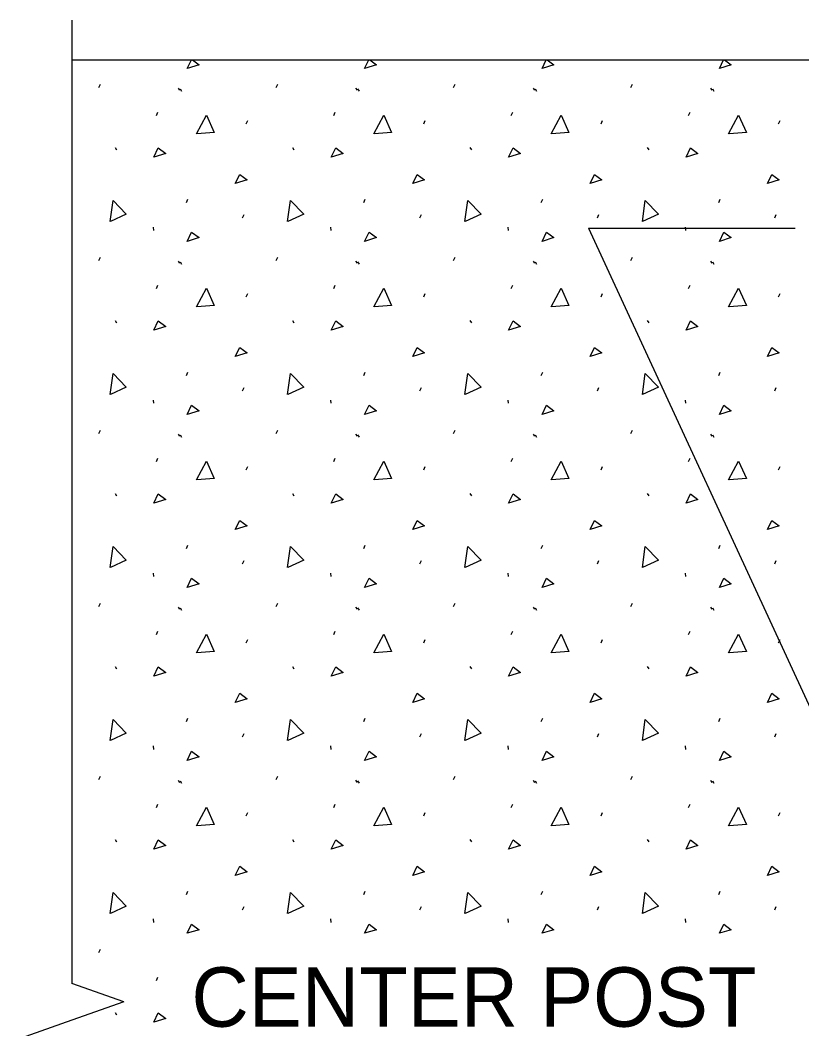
# Model space of a CAD drawing. Extents: x 49991.4 to 50021, y 49987.6 to 50011.4.
# Drawn here: x 50009.655 to 50010.444, y 49996.152 to 49997.171 of the extents above; entities that cross this region are included whole.
import ezdxf

# ---------------------------------------------------------------- set-up
doc = ezdxf.new("R2010")
doc.units = 0
for name, color, linetype in [('Level 1', 7, 'Continuous'), ('Level 2', 7, 'Continuous'), ('Level 3', 7, 'Continuous'), ('Level 6', 7, 'Continuous')]:
    doc.layers.add(name, color=color, linetype=linetype)

msp = doc.modelspace()

# ---------------------------------------------------------------- linework, layer by layer
at = {"layer": 'Level 1'}
for p, q in [((50009.7073, 49997.1307), (50012.0351, 49997.1307)), ((50009.8237, 49997.122), (50009.8279, 49997.1307)), ((50010.0029, 49997.122), (50010.0071, 49997.1307)), ((50010.1821, 49997.122), (50010.1862, 49997.1307)), ((50010.3612, 49997.122), (50010.3654, 49997.1307)), ((50009.7345, 49997.1026), (50009.736, 49997.1059)), ((50009.8146, 49997.1021), (50009.8161, 49997.0998)), ((50009.8166, 49997.1012), (50009.8181, 49997.099)), ((50009.9136, 49997.1026), (50009.9151, 49997.1059)), ((50009.9938, 49997.1021), (50009.9953, 49997.0998)), ((50009.9958, 49997.1012), (50009.9973, 49997.099)), ((50010.0928, 49997.1026), (50010.0943, 49997.1059)), ((50010.173, 49997.1021), (50010.1745, 49997.0998)), ((50010.175, 49997.1012), (50010.1765, 49997.099)), ((50010.2719, 49997.1026), (50010.2734, 49997.1059)), ((50010.3521, 49997.1021), (50010.3536, 49997.0998)), ((50010.3541, 49997.1012), (50010.3556, 49997.099)), ((50009.7926, 49997.0744), (50009.7941, 49997.0778)), ((50009.9718, 49997.0744), (50009.9733, 49997.0778)), ((50010.151, 49997.0744), (50010.1525, 49997.0778)), ((50010.3301, 49997.0744), (50010.3316, 49997.0778)), ((50009.8834, 49997.0658), (50009.8849, 49997.0692)), ((50010.0626, 49997.0658), (50010.0641, 49997.0692)), ((50010.2417, 49997.0658), (50010.2432, 49997.0692)), ((50010.4209, 49997.0658), (50010.4224, 49997.0692)), ((50009.7509, 49997.042), (50009.7524, 49997.0397)), ((50009.79, 49997.0323), (50009.7945, 49997.0416)), ((50009.7945, 49997.0416), (50009.802, 49997.036)), ((50009.93, 49997.042), (50009.9315, 49997.0397)), ((50009.9692, 49997.0323), (50009.9737, 49997.0416)), ((50009.9737, 49997.0416), (50009.9811, 49997.036)), ((50010.1092, 49997.042), (50010.1107, 49997.0397)), ((50010.1483, 49997.0323), (50010.1528, 49997.0416)), ((50010.1528, 49997.0416), (50010.1603, 49997.036)), ((50010.2883, 49997.042), (50010.2898, 49997.0397)), ((50010.3275, 49997.0323), (50010.332, 49997.0416)), ((50010.332, 49997.0416), (50010.3394, 49997.036)), ((50009.802, 49997.036), (50009.79, 49997.0323)), ((50009.9811, 49997.036), (50009.9692, 49997.0323)), ((50010.1603, 49997.036), (50010.1483, 49997.0323)), ((50010.3394, 49997.036), (50010.3275, 49997.0323)), ((50009.823, 49996.9864), (50009.8245, 49996.9898)), ((50010.0021, 49996.9864), (50010.0036, 49996.9898)), ((50010.1813, 49996.9864), (50010.1828, 49996.9898)), ((50010.3605, 49996.9864), (50010.362, 49996.9898)), ((50009.8797, 49996.9711), (50009.8812, 49996.9745)), ((50010.0588, 49996.9711), (50010.0603, 49996.9745)), ((50010.238, 49996.9711), (50010.2395, 49996.9745)), ((50010.4172, 49996.9711), (50010.4186, 49996.9745)), ((50009.7892, 49996.9617), (50009.7896, 49996.9584)), ((50009.9684, 49996.9617), (50009.9687, 49996.9584)), ((50010.1475, 49996.9617), (50010.1479, 49996.9584)), ((50010.3267, 49996.9617), (50010.327, 49996.9584)), ((50009.7345, 49996.9278), (50009.736, 49996.9312)), ((50009.8146, 49996.9273), (50009.8161, 49996.9251)), ((50009.8166, 49996.9265), (50009.8181, 49996.9243)), ((50009.9136, 49996.9278), (50009.9151, 49996.9312)), ((50009.9938, 49996.9273), (50009.9953, 49996.9251)), ((50009.9958, 49996.9265), (50009.9973, 49996.9243)), ((50010.0928, 49996.9278), (50010.0943, 49996.9312)), ((50010.173, 49996.9273), (50010.1745, 49996.9251)), ((50010.175, 49996.9265), (50010.1765, 49996.9243)), ((50010.2719, 49996.9278), (50010.2734, 49996.9312)), ((50010.3521, 49996.9273), (50010.3536, 49996.9251)), ((50010.3541, 49996.9265), (50010.3556, 49996.9243)), ((50009.7926, 49996.8997), (50009.7941, 49996.9031)), ((50009.8834, 49996.8911), (50009.8849, 49996.8945)), ((50009.9718, 49996.8997), (50009.9733, 49996.9031)), ((50010.0626, 49996.8911), (50010.0641, 49996.8945)), ((50010.151, 49996.8997), (50010.1525, 49996.9031)), ((50010.2417, 49996.8911), (50010.2432, 49996.8945)), ((50010.3301, 49996.8997), (50010.3316, 49996.9031)), ((50010.4209, 49996.8911), (50010.4224, 49996.8945)), ((50009.7509, 49996.8673), (50009.7524, 49996.865)), ((50009.79, 49996.8576), (50009.7945, 49996.8669)), ((50009.7945, 49996.8669), (50009.802, 49996.8613)), ((50009.93, 49996.8673), (50009.9315, 49996.865)), ((50009.9692, 49996.8576), (50009.9737, 49996.8669)), ((50009.9737, 49996.8669), (50009.9811, 49996.8613)), ((50010.1092, 49996.8673), (50010.1107, 49996.865)), ((50010.1483, 49996.8576), (50010.1528, 49996.8669)), ((50010.1528, 49996.8669), (50010.1603, 49996.8613)), ((50010.2883, 49996.8673), (50010.2898, 49996.865)), ((50010.3275, 49996.8576), (50010.332, 49996.8669)), ((50010.332, 49996.8669), (50010.3394, 49996.8613)), ((50009.802, 49996.8613), (50009.79, 49996.8576)), ((50009.9811, 49996.8613), (50009.9692, 49996.8576)), ((50010.1603, 49996.8613), (50010.1483, 49996.8576)), ((50010.3394, 49996.8613), (50010.3275, 49996.8576)), ((50009.823, 49996.8117), (50009.8245, 49996.815)), ((50010.0021, 49996.8117), (50010.0036, 49996.815)), ((50010.1813, 49996.8117), (50010.1828, 49996.815)), ((50010.3605, 49996.8117), (50010.362, 49996.815)), ((50009.8797, 49996.7964), (50009.8812, 49996.7997)), ((50010.0588, 49996.7964), (50010.0603, 49996.7997)), ((50010.238, 49996.7964), (50010.2395, 49996.7997)), ((50010.4172, 49996.7964), (50010.4186, 49996.7997)), ((50009.7892, 49996.787), (50009.7896, 49996.7837)), ((50009.9684, 49996.787), (50009.9687, 49996.7837)), ((50010.1475, 49996.787), (50010.1479, 49996.7837)), ((50010.3267, 49996.787), (50010.327, 49996.7837)), ((50009.7345, 49996.7531), (50009.736, 49996.7565)), ((50009.8146, 49996.7526), (50009.8161, 49996.7504)), ((50009.8166, 49996.7518), (50009.8181, 49996.7495)), ((50009.9136, 49996.7531), (50009.9151, 49996.7565)), ((50009.9938, 49996.7526), (50009.9953, 49996.7504)), ((50009.9958, 49996.7518), (50009.9973, 49996.7495)), ((50010.0928, 49996.7531), (50010.0943, 49996.7565)), ((50010.173, 49996.7526), (50010.1745, 49996.7504)), ((50010.175, 49996.7518), (50010.1765, 49996.7495)), ((50010.2719, 49996.7531), (50010.2734, 49996.7565)), ((50010.3521, 49996.7526), (50010.3536, 49996.7504)), ((50010.3541, 49996.7518), (50010.3556, 49996.7495)), ((50009.7926, 49996.725), (50009.7941, 49996.7283)), ((50009.9718, 49996.725), (50009.9733, 49996.7283)), ((50010.151, 49996.725), (50010.1525, 49996.7283)), ((50010.3301, 49996.725), (50010.3316, 49996.7283)), ((50009.8834, 49996.7164), (50009.8849, 49996.7198)), ((50010.0626, 49996.7164), (50010.0641, 49996.7198)), ((50010.2417, 49996.7164), (50010.2432, 49996.7198)), ((50010.4209, 49996.7164), (50010.4224, 49996.7198)), ((50009.7509, 49996.6925), (50009.7524, 49996.6903)), ((50009.79, 49996.6828), (50009.7945, 49996.6922)), ((50009.7945, 49996.6922), (50009.802, 49996.6866)), ((50009.93, 49996.6925), (50009.9315, 49996.6903)), ((50009.9692, 49996.6828), (50009.9737, 49996.6922)), ((50009.9737, 49996.6922), (50009.9811, 49996.6866)), ((50010.1092, 49996.6925), (50010.1107, 49996.6903)), ((50010.1483, 49996.6828), (50010.1528, 49996.6922)), ((50010.1528, 49996.6922), (50010.1603, 49996.6866)), ((50010.2883, 49996.6925), (50010.2898, 49996.6903)), ((50010.3275, 49996.6828), (50010.332, 49996.6922)), ((50010.332, 49996.6922), (50010.3394, 49996.6866)), ((50009.802, 49996.6866), (50009.79, 49996.6828)), ((50009.9811, 49996.6866), (50009.9692, 49996.6828)), ((50010.1603, 49996.6866), (50010.1483, 49996.6828)), ((50010.3394, 49996.6866), (50010.3275, 49996.6828)), ((50009.823, 49996.637), (50009.8245, 49996.6403)), ((50010.0021, 49996.637), (50010.0036, 49996.6403)), ((50010.1813, 49996.637), (50010.1828, 49996.6403)), ((50010.3605, 49996.637), (50010.362, 49996.6403)), ((50009.8797, 49996.6217), (50009.8812, 49996.625)), ((50010.0588, 49996.6217), (50010.0603, 49996.625)), ((50010.238, 49996.6217), (50010.2395, 49996.625)), ((50010.4172, 49996.6217), (50010.4186, 49996.625)), ((50009.7892, 49996.6123), (50009.7896, 49996.6089)), ((50009.9684, 49996.6123), (50009.9687, 49996.6089)), ((50010.1475, 49996.6123), (50010.1479, 49996.6089)), ((50010.3267, 49996.6123), (50010.327, 49996.6089)), ((50009.7345, 49996.5784), (50009.736, 49996.5818)), ((50009.8146, 49996.5779), (50009.8161, 49996.5757)), ((50009.9136, 49996.5784), (50009.9151, 49996.5818)), ((50009.9938, 49996.5779), (50009.9953, 49996.5757)), ((50010.0928, 49996.5784), (50010.0943, 49996.5818)), ((50010.173, 49996.5779), (50010.1745, 49996.5757)), ((50010.2719, 49996.5784), (50010.2734, 49996.5818)), ((50010.3521, 49996.5779), (50010.3536, 49996.5757)), ((50009.8166, 49996.5771), (50009.8181, 49996.5748)), ((50009.9958, 49996.5771), (50009.9973, 49996.5748)), ((50010.175, 49996.5771), (50010.1765, 49996.5748)), ((50010.3541, 49996.5771), (50010.3556, 49996.5748)), ((50009.7926, 49996.5503), (50009.7941, 49996.5536)), ((50009.9718, 49996.5503), (50009.9733, 49996.5536)), ((50010.151, 49996.5503), (50010.1525, 49996.5536)), ((50010.3301, 49996.5503), (50010.3316, 49996.5536)), ((50009.8834, 49996.5417), (50009.8849, 49996.545)), ((50010.0626, 49996.5417), (50010.0641, 49996.545)), ((50010.2417, 49996.5417), (50010.2432, 49996.545)), ((50010.4209, 49996.5417), (50010.4224, 49996.545)), ((50009.7509, 49996.5178), (50009.7524, 49996.5156)), ((50009.79, 49996.5081), (50009.7945, 49996.5174)), ((50009.7945, 49996.5174), (50009.802, 49996.5118)), ((50009.93, 49996.5178), (50009.9315, 49996.5156)), ((50009.9692, 49996.5081), (50009.9737, 49996.5174)), ((50009.9737, 49996.5174), (50009.9811, 49996.5118)), ((50010.1092, 49996.5178), (50010.1107, 49996.5156)), ((50010.1483, 49996.5081), (50010.1528, 49996.5174)), ((50010.1528, 49996.5174), (50010.1603, 49996.5118)), ((50010.2883, 49996.5178), (50010.2898, 49996.5156)), ((50010.3275, 49996.5081), (50010.332, 49996.5174)), ((50010.332, 49996.5174), (50010.3394, 49996.5118)), ((50009.802, 49996.5118), (50009.79, 49996.5081)), ((50009.9811, 49996.5118), (50009.9692, 49996.5081)), ((50010.1603, 49996.5118), (50010.1483, 49996.5081)), ((50010.3394, 49996.5118), (50010.3275, 49996.5081)), ((50009.823, 49996.4622), (50009.8245, 49996.4656)), ((50010.0021, 49996.4622), (50010.0036, 49996.4656)), ((50010.1813, 49996.4622), (50010.1828, 49996.4656)), ((50010.3605, 49996.4622), (50010.362, 49996.4656)), ((50009.8797, 49996.4469), (50009.8812, 49996.4503)), ((50010.0588, 49996.4469), (50010.0603, 49996.4503)), ((50010.238, 49996.4469), (50010.2395, 49996.4503)), ((50010.4172, 49996.4469), (50010.4186, 49996.4503)), ((50009.7892, 49996.4376), (50009.7896, 49996.4342)), ((50009.9684, 49996.4376), (50009.9687, 49996.4342)), ((50010.1475, 49996.4376), (50010.1479, 49996.4342)), ((50010.3267, 49996.4376), (50010.327, 49996.4342)), ((50009.7345, 49996.4037), (50009.736, 49996.407)), ((50009.9136, 49996.4037), (50009.9151, 49996.407)), ((50010.0928, 49996.4037), (50010.0943, 49996.407)), ((50010.2719, 49996.4037), (50010.2734, 49996.407)), ((50009.8146, 49996.4032), (50009.8161, 49996.4009)), ((50009.8166, 49996.4023), (50009.8181, 49996.4001)), ((50009.9938, 49996.4032), (50009.9953, 49996.4009)), ((50009.9958, 49996.4023), (50009.9973, 49996.4001)), ((50010.173, 49996.4032), (50010.1745, 49996.4009)), ((50010.175, 49996.4023), (50010.1765, 49996.4001)), ((50010.3521, 49996.4032), (50010.3536, 49996.4009)), ((50010.3541, 49996.4023), (50010.3556, 49996.4001)), ((50009.7926, 49996.3755), (50009.7941, 49996.3789)), ((50009.9718, 49996.3755), (50009.9733, 49996.3789)), ((50010.151, 49996.3755), (50010.1525, 49996.3789)), ((50010.3301, 49996.3755), (50010.3316, 49996.3789)), ((50009.8834, 49996.367), (50009.8849, 49996.3703)), ((50010.0626, 49996.367), (50010.0641, 49996.3703)), ((50010.2417, 49996.367), (50010.2432, 49996.3703)), ((50010.4209, 49996.367), (50010.4224, 49996.3703)), ((50009.7509, 49996.3431), (50009.7524, 49996.3409)), ((50009.79, 49996.3334), (50009.7945, 49996.3427)), ((50009.802, 49996.3371), (50009.79, 49996.3334)), ((50009.7945, 49996.3427), (50009.802, 49996.3371)), ((50009.93, 49996.3431), (50009.9315, 49996.3409)), ((50009.9692, 49996.3334), (50009.9737, 49996.3427)), ((50009.9811, 49996.3371), (50009.9692, 49996.3334)), ((50009.9737, 49996.3427), (50009.9811, 49996.3371)), ((50010.1092, 49996.3431), (50010.1107, 49996.3409)), ((50010.1483, 49996.3334), (50010.1528, 49996.3427)), ((50010.1603, 49996.3371), (50010.1483, 49996.3334)), ((50010.1528, 49996.3427), (50010.1603, 49996.3371)), ((50010.2883, 49996.3431), (50010.2898, 49996.3409)), ((50010.3275, 49996.3334), (50010.332, 49996.3427)), ((50010.3394, 49996.3371), (50010.3275, 49996.3334)), ((50010.332, 49996.3427), (50010.3394, 49996.3371)), ((50009.823, 49996.2875), (50009.8245, 49996.2909)), ((50010.0021, 49996.2875), (50010.0036, 49996.2909)), ((50010.1813, 49996.2875), (50010.1828, 49996.2909)), ((50010.3605, 49996.2875), (50010.362, 49996.2909)), ((50009.8797, 49996.2722), (50009.8812, 49996.2756)), ((50010.0588, 49996.2722), (50010.0603, 49996.2756)), ((50010.238, 49996.2722), (50010.2395, 49996.2756)), ((50010.4172, 49996.2722), (50010.4186, 49996.2756)), ((50009.7892, 49996.2629), (50009.7896, 49996.2595)), ((50009.9684, 49996.2629), (50009.9687, 49996.2595)), ((50010.1475, 49996.2629), (50010.1479, 49996.2595)), ((50010.3267, 49996.2629), (50010.327, 49996.2595)), ((50009.7345, 49996.229), (50009.736, 49996.2323)), ((50009.7926, 49996.2008), (50009.7941, 49996.2042)), ((50009.7509, 49996.1684), (50009.7524, 49996.1661)), ((50009.79, 49996.1587), (50009.7945, 49996.168)), ((50009.802, 49996.1624), (50009.79, 49996.1587)), ((50009.7945, 49996.168), (50009.802, 49996.1624))]:
    msp.add_line(p, q, dxfattribs=at)
for points in [[(50009.8291, 49997.1307), (50009.8357, 49997.1257), (50009.8237, 49997.122)], [(50010.0082, 49997.1307), (50010.0148, 49997.1257), (50010.0029, 49997.122)], [(50010.1874, 49997.1307), (50010.194, 49997.1257), (50010.1821, 49997.122)], [(50010.3665, 49997.1307), (50010.3731, 49997.1257), (50010.3612, 49997.122)], [(50009.8331, 49997.0558), (50009.8431, 49997.0748), (50009.851, 49997.0573), (50009.8334, 49997.0558)], [(50010.0122, 49997.0558), (50010.0223, 49997.0748), (50010.0301, 49997.0573), (50010.0126, 49997.0558)], [(50010.1914, 49997.0558), (50010.2014, 49997.0748), (50010.2093, 49997.0573), (50010.1917, 49997.0558)], [(50010.3705, 49997.0558), (50010.3806, 49997.0748), (50010.3884, 49997.0573), (50010.3709, 49997.0558)], [(50009.8723, 49997.0056), (50009.8768, 49997.0149), (50009.8842, 49997.0093), (50009.8723, 49997.0056)], [(50010.0515, 49997.0056), (50010.0559, 49997.0149), (50010.0634, 49997.0093), (50010.0515, 49997.0056)], [(50010.2306, 49997.0056), (50010.2351, 49997.0149), (50010.2425, 49997.0093), (50010.2306, 49997.0056)], [(50010.4098, 49997.0056), (50010.4142, 49997.0149), (50010.4217, 49997.0093), (50010.4098, 49997.0056)], [(50009.7459, 49996.9673), (50009.7488, 49996.9886), (50009.7622, 49996.9748), (50009.7462, 49996.9674)], [(50009.9251, 49996.9673), (50009.928, 49996.9886), (50009.9414, 49996.9748), (50009.9254, 49996.9674)], [(50010.1042, 49996.9673), (50010.1072, 49996.9886), (50010.1205, 49996.9748), (50010.1046, 49996.9674)], [(50010.2834, 49996.9673), (50010.2863, 49996.9886), (50010.2997, 49996.9748), (50010.2837, 49996.9674)], [(50009.8237, 49996.9472), (50009.8282, 49996.9566), (50009.8357, 49996.951), (50009.8237, 49996.9472)], [(50010.0029, 49996.9472), (50010.0074, 49996.9566), (50010.0148, 49996.951), (50010.0029, 49996.9472)], [(50010.1821, 49996.9472), (50010.1865, 49996.9566), (50010.194, 49996.951), (50010.1821, 49996.9472)], [(50010.3612, 49996.9472), (50010.3657, 49996.9566), (50010.3731, 49996.951), (50010.3612, 49996.9472)], [(50009.8331, 49996.8811), (50009.8431, 49996.9001), (50009.851, 49996.8825), (50009.8334, 49996.8811)], [(50010.0122, 49996.8811), (50010.0223, 49996.9001), (50010.0301, 49996.8825), (50010.0126, 49996.8811)], [(50010.1914, 49996.8811), (50010.2014, 49996.9001), (50010.2093, 49996.8825), (50010.1917, 49996.8811)], [(50010.3705, 49996.8811), (50010.3806, 49996.9001), (50010.3884, 49996.8825), (50010.3709, 49996.8811)], [(50009.8723, 49996.8309), (50009.8768, 49996.8402), (50009.8842, 49996.8346), (50009.8723, 49996.8309)], [(50010.0515, 49996.8309), (50010.0559, 49996.8402), (50010.0634, 49996.8346), (50010.0515, 49996.8309)], [(50010.2306, 49996.8309), (50010.2351, 49996.8402), (50010.2425, 49996.8346), (50010.2306, 49996.8309)], [(50010.4098, 49996.8309), (50010.4142, 49996.8402), (50010.4217, 49996.8346), (50010.4098, 49996.8309)], [(50009.7459, 49996.7925), (50009.7488, 49996.8138), (50009.7622, 49996.8001), (50009.7462, 49996.7927)], [(50009.9251, 49996.7925), (50009.928, 49996.8138), (50009.9414, 49996.8001), (50009.9254, 49996.7927)], [(50010.1042, 49996.7925), (50010.1072, 49996.8138), (50010.1205, 49996.8001), (50010.1046, 49996.7927)], [(50010.2834, 49996.7925), (50010.2863, 49996.8138), (50010.2997, 49996.8001), (50010.2837, 49996.7927)], [(50009.8237, 49996.7725), (50009.8282, 49996.7818), (50009.8357, 49996.7762), (50009.8237, 49996.7725)], [(50010.0029, 49996.7725), (50010.0074, 49996.7818), (50010.0148, 49996.7762), (50010.0029, 49996.7725)], [(50010.1821, 49996.7725), (50010.1865, 49996.7818), (50010.194, 49996.7762), (50010.1821, 49996.7725)], [(50010.3612, 49996.7725), (50010.3657, 49996.7818), (50010.3731, 49996.7762), (50010.3612, 49996.7725)], [(50009.8331, 49996.7063), (50009.8431, 49996.7254), (50009.851, 49996.7078), (50009.8334, 49996.7063)], [(50010.0122, 49996.7063), (50010.0223, 49996.7254), (50010.0301, 49996.7078), (50010.0126, 49996.7063)], [(50010.1914, 49996.7063), (50010.2014, 49996.7254), (50010.2093, 49996.7078), (50010.1917, 49996.7063)], [(50010.3705, 49996.7063), (50010.3806, 49996.7254), (50010.3884, 49996.7078), (50010.3709, 49996.7063)], [(50009.8723, 49996.6562), (50009.8768, 49996.6655), (50009.8842, 49996.6599), (50009.8723, 49996.6562)], [(50010.0515, 49996.6562), (50010.0559, 49996.6655), (50010.0634, 49996.6599), (50010.0515, 49996.6562)], [(50010.2306, 49996.6562), (50010.2351, 49996.6655), (50010.2425, 49996.6599), (50010.2306, 49996.6562)], [(50010.4098, 49996.6562), (50010.4142, 49996.6655), (50010.4217, 49996.6599), (50010.4098, 49996.6562)], [(50009.7459, 49996.6178), (50009.7488, 49996.6391), (50009.7622, 49996.6253), (50009.7462, 49996.6179)], [(50009.9251, 49996.6178), (50009.928, 49996.6391), (50009.9414, 49996.6253), (50009.9254, 49996.6179)], [(50010.1042, 49996.6178), (50010.1072, 49996.6391), (50010.1205, 49996.6253), (50010.1046, 49996.6179)], [(50010.2834, 49996.6178), (50010.2863, 49996.6391), (50010.2997, 49996.6253), (50010.2837, 49996.6179)], [(50009.8237, 49996.5978), (50009.8282, 49996.6071), (50009.8357, 49996.6015), (50009.8237, 49996.5978)], [(50010.0029, 49996.5978), (50010.0074, 49996.6071), (50010.0148, 49996.6015), (50010.0029, 49996.5978)], [(50010.1821, 49996.5978), (50010.1865, 49996.6071), (50010.194, 49996.6015), (50010.1821, 49996.5978)], [(50010.3612, 49996.5978), (50010.3657, 49996.6071), (50010.3731, 49996.6015), (50010.3612, 49996.5978)], [(50009.8331, 49996.5316), (50009.8431, 49996.5506), (50009.851, 49996.5331), (50009.8334, 49996.5316)], [(50010.0122, 49996.5316), (50010.0223, 49996.5506), (50010.0301, 49996.5331), (50010.0126, 49996.5316)], [(50010.1914, 49996.5316), (50010.2014, 49996.5506), (50010.2093, 49996.5331), (50010.1917, 49996.5316)], [(50010.3705, 49996.5316), (50010.3806, 49996.5506), (50010.3884, 49996.5331), (50010.3709, 49996.5316)], [(50009.8723, 49996.4815), (50009.8768, 49996.4908), (50009.8842, 49996.4852), (50009.8723, 49996.4815)], [(50010.0515, 49996.4815), (50010.0559, 49996.4908), (50010.0634, 49996.4852), (50010.0515, 49996.4815)], [(50010.2306, 49996.4815), (50010.2351, 49996.4908), (50010.2425, 49996.4852), (50010.2306, 49996.4815)], [(50010.4098, 49996.4815), (50010.4142, 49996.4908), (50010.4217, 49996.4852), (50010.4098, 49996.4815)], [(50009.7459, 49996.4431), (50009.7488, 49996.4644), (50009.7622, 49996.4506), (50009.7462, 49996.4432)], [(50009.9251, 49996.4431), (50009.928, 49996.4644), (50009.9414, 49996.4506), (50009.9254, 49996.4432)], [(50010.1042, 49996.4431), (50010.1072, 49996.4644), (50010.1205, 49996.4506), (50010.1046, 49996.4432)], [(50010.2834, 49996.4431), (50010.2863, 49996.4644), (50010.2997, 49996.4506), (50010.2837, 49996.4432)], [(50009.8237, 49996.4231), (50009.8282, 49996.4324), (50009.8357, 49996.4268), (50009.8237, 49996.4231)], [(50010.0029, 49996.4231), (50010.0074, 49996.4324), (50010.0148, 49996.4268), (50010.0029, 49996.4231)], [(50010.1821, 49996.4231), (50010.1865, 49996.4324), (50010.194, 49996.4268), (50010.1821, 49996.4231)], [(50010.3612, 49996.4231), (50010.3657, 49996.4324), (50010.3731, 49996.4268), (50010.3612, 49996.4231)], [(50009.8331, 49996.3569), (50009.8431, 49996.3759), (50009.851, 49996.3584), (50009.8334, 49996.3569)], [(50010.0122, 49996.3569), (50010.0223, 49996.3759), (50010.0301, 49996.3584), (50010.0126, 49996.3569)], [(50010.1914, 49996.3569), (50010.2014, 49996.3759), (50010.2093, 49996.3584), (50010.1917, 49996.3569)], [(50010.3705, 49996.3569), (50010.3806, 49996.3759), (50010.3884, 49996.3584), (50010.3709, 49996.3569)], [(50009.8723, 49996.3067), (50009.8768, 49996.3161), (50009.8842, 49996.3105), (50009.8723, 49996.3067)], [(50010.0515, 49996.3067), (50010.0559, 49996.3161), (50010.0634, 49996.3105), (50010.0515, 49996.3067)], [(50010.2306, 49996.3067), (50010.2351, 49996.3161), (50010.2425, 49996.3105), (50010.2306, 49996.3067)], [(50010.4098, 49996.3067), (50010.4142, 49996.3161), (50010.4217, 49996.3105), (50010.4098, 49996.3067)], [(50009.7459, 49996.2684), (50009.7488, 49996.2897), (50009.7622, 49996.2759), (50009.7462, 49996.2685)], [(50009.9251, 49996.2684), (50009.928, 49996.2897), (50009.9414, 49996.2759), (50009.9254, 49996.2685)], [(50010.1042, 49996.2684), (50010.1072, 49996.2897), (50010.1205, 49996.2759), (50010.1046, 49996.2685)], [(50010.2834, 49996.2684), (50010.2863, 49996.2897), (50010.2997, 49996.2759), (50010.2837, 49996.2685)], [(50009.8237, 49996.2484), (50009.8282, 49996.2577), (50009.8357, 49996.2521), (50009.8237, 49996.2484)], [(50010.0029, 49996.2484), (50010.0074, 49996.2577), (50010.0148, 49996.2521), (50010.0029, 49996.2484)], [(50010.1821, 49996.2484), (50010.1865, 49996.2577), (50010.194, 49996.2521), (50010.1821, 49996.2484)], [(50010.3612, 49996.2484), (50010.3657, 49996.2577), (50010.3731, 49996.2521), (50010.3612, 49996.2484)]]:
    msp.add_lwpolyline(points, dxfattribs=at)
at = {"layer": 'Level 3'}
for q in [(50010.5512, 49996.2631), (50010.4378, 49996.9607)]:
    msp.add_line((50010.2289, 49996.9607), q, dxfattribs=at)
at = {"layer": 'Level 6'}
for p, q in [((50009.7073, 49997.1707), (50009.7073, 49996.3166)), ((50009.7073, 49996.3166), (50009.7073, 49996.1977)), ((50009.7597, 49996.1792), (50009.7073, 49996.1977)), ((50009.7597, 49996.1792), (50009.7073, 49996.1606)), ((50009.7073, 49996.1606), (50009.655, 49996.1421))]:
    msp.add_line(p, q, dxfattribs=at)

# ---------------------------------------------------------------- texts
at = {"layer": 'Level 2'}
msp.add_text('CENTER POST', height=0.06, dxfattribs=at).set_placement((50009.828, 49996.1541))

doc.saveas('drawing.dxf')
